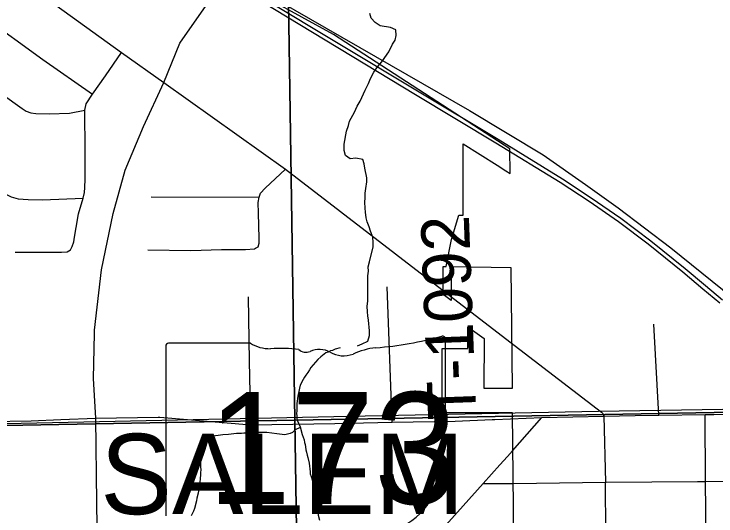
# Model space of a CAD drawing. Extents: x 0 to 34, y 0 to 22.
# Drawn here: x 4.199 to 5.027, y 17.129 to 17.721 of the extents above; entities that cross this region are included whole.
import ezdxf

# ---------------------------------------------------------------- set-up
doc = ezdxf.new("R2010")
doc.units = 0
for name, color, linetype in [('GM_X_City_Street', 7, 'Continuous'), ('GM_X_Corporation', 7, 'Continuous'), ('GM_X_Corporation_Text', 7, 'Continuous'), ('GM_X_County_Road', 7, 'Continuous'), ('GM_X_Minor_River', 7, 'Continuous'), ('GM_X_Rail_Line', 7, 'Continuous'), ('GM_X_Section', 7, 'Continuous'), ('GM_X_State_Location', 7, 'Continuous'), ('GM_X_State_Route', 7, 'Continuous'), ('GM_X_State_Shield', 7, 'Continuous'), ('GM_X_Township_Road', 7, 'Continuous'), ('GM_X_Township_Road_Text', 7, 'Continuous'), ('GM_X_US_Route', 7, 'Continuous')]:
    doc.layers.add(name, color=color, linetype=linetype)

msp = doc.modelspace()

# ---------------------------------------------------------------- linework, layer by layer
at = {"layer": 'GM_X_City_Street'}
for p, q in [((4.95935, 17.24777), (4.95332, 17.3552)), ((4.78787, 17.16729), (4.89625, 17.16873)), ((4.89686, 17.10104), (4.89625, 17.16873))]:
    msp.add_line(p, q, dxfattribs=at)
for points in [[(4.1481, 17.94458), (4.22468, 17.90127), (4.45612, 17.76798), (4.73588, 17.60688), (4.82274, 17.55459), (4.87294, 17.51962), (4.91128, 17.49207), (4.9734, 17.44512), (5.03441, 17.39587), (5.09354, 17.34622), (5.10314, 17.338), (5.1112, 17.33166), (5.11389, 17.32904), (5.1162, 17.32679)], [(5.01789, 16.75647), (5.01713, 16.84532), (5.01705, 16.85489), (5.01646, 16.92439), (5.01497, 17.10166), (5.01439, 17.16951), (5.01372, 17.24856)]]:
    msp.add_lwpolyline(points, dxfattribs=at)
at = {"layer": 'GM_X_Corporation'}
msp.add_lwpolyline([(4.7933, 16.6174), (4.78685, 17.25042), (4.74798, 17.25045), (4.70383, 17.25048), (4.70388, 17.32626), (4.73419, 17.32624), (4.7342, 17.35191), (4.75314, 17.33805), (4.7531, 17.27963), (4.78655, 17.27961), (4.78511, 17.42147), (4.71434, 17.42275), (4.71431, 17.38297), (4.70506, 17.39021), (4.70508, 17.42298), (4.70849, 17.42292), (4.7147, 17.45471), (4.72358, 17.48369), (4.72851, 17.4836), (4.72856, 17.56772), (4.76855, 17.54269), (4.77899, 17.53591), (4.78398, 17.53266), (4.78368, 17.56184), (4.57553, 17.69648), (4.50108, 17.73775)], dxfattribs=at)
at = {"layer": 'GM_X_County_Road'}
for p, q in [((4.8943, 17.24683), (4.89625, 17.16873)), ((4.78655, 17.2058), (4.82128, 17.24488))]:
    msp.add_line(p, q, dxfattribs=at)
for points in [[(4.30411, 16.68523), (4.39551, 16.6873), (4.41229, 16.68968), (4.4267, 16.69428), (4.44068, 16.6996), (4.45473, 16.71024), (4.46516, 16.71819), (4.47258, 16.72621), (4.47852, 16.73334), (4.58068, 16.92928), (4.59524, 16.96194), (4.60504, 16.97976), (4.61588, 17.00129), (4.62182, 17.01229), (4.63013, 17.02431), (4.65416, 17.05807), (4.75214, 17.16729), (4.77199, 17.18941), (4.78076, 17.19929), (4.78655, 17.2058)], [(5.00672, 17.16946), (5.01439, 17.16951), (5.16951, 17.17054), (5.1907, 17.17089), (5.22212, 17.17103), (5.46565, 17.18259), (5.54242, 17.1836)], [(4.89625, 17.16873), (4.89724, 17.16873), (5.00477, 17.16945)], [(5.00477, 17.16945), (5.00576, 17.16946), (5.00672, 17.16946)]]:
    msp.add_lwpolyline(points, dxfattribs=at)
at = {"layer": 'GM_X_Minor_River'}
for points in [[(4.60418, 17.32971), (4.60969, 17.33192), (4.61606, 17.3351), (4.61819, 17.34161), (4.61806, 17.34731), (4.61702, 17.35982), (4.61616, 17.36475), (4.61566, 17.36967), (4.61552, 17.37613), (4.61614, 17.38223), (4.616, 17.3883), (4.61623, 17.39515), (4.616, 17.4054), (4.61623, 17.41187), (4.61686, 17.41758), (4.61675, 17.42252), (4.61813, 17.42863), (4.61916, 17.4336), (4.6223, 17.44583), (4.62255, 17.45153), (4.62203, 17.4576), (4.61921, 17.46476), (4.61759, 17.46966), (4.61555, 17.4757), (4.61431, 17.48061), (4.6134, 17.48705), (4.61291, 17.49198), (4.61276, 17.49882), (4.61302, 17.50414), (4.6129, 17.50946), (4.61391, 17.51518), (4.61487, 17.52281), (4.61514, 17.52775), (4.61261, 17.5391), (4.61174, 17.54402), (4.61011, 17.5493), (4.60211, 17.55064), (4.5953, 17.55011), (4.58991, 17.55378), (4.58825, 17.55983), (4.58846, 17.56743), (4.59115, 17.5827), (4.59328, 17.5892), (4.59469, 17.59418), (4.60051, 17.60495), (4.60376, 17.61224), (4.60705, 17.61802), (4.6132, 17.63107), (4.61682, 17.63876), (4.61934, 17.64451), (4.62334, 17.65221), (4.62776, 17.65839), (4.63255, 17.66419), (4.63623, 17.6696), (4.64101, 17.67617), (4.64536, 17.685), (4.64828, 17.69001), (4.64968, 17.69536), (4.64915, 17.70219), (4.64302, 17.70471), (4.63084, 17.70672), (4.62468, 17.71076), (4.62001, 17.71597), (4.61838, 17.72126)], [(4.58337, 17.32733), (4.57774, 17.32557), (4.57472, 17.32402), (4.57207, 17.32361), (4.56943, 17.32206), (4.56679, 17.32126), (4.56077, 17.31663), (4.55739, 17.31355), (4.54916, 17.30395), (4.54729, 17.30127), (4.54543, 17.29821), (4.54319, 17.29514), (4.54171, 17.29247), (4.53984, 17.28978), (4.5365, 17.28328), (4.53578, 17.27947), (4.53362, 17.27033), (4.53258, 17.26158), (4.53265, 17.2555), (4.5323, 17.25283), (4.53195, 17.24979), (4.53236, 17.24713), (4.53239, 17.24447), (4.5328, 17.24182), (4.53631, 17.23388), (4.53868, 17.22517), (4.54103, 17.21873), (4.54145, 17.2157), (4.54223, 17.21305), (4.54264, 17.21039), (4.54306, 17.20698), (4.54385, 17.20432), (4.54465, 17.20053), (4.54544, 17.19788), (4.54704, 17.19106), (4.54829, 17.1812), (4.54832, 17.17854), (4.54949, 17.17551), (4.55303, 17.16415), (4.55382, 17.1615), (4.55503, 17.15506), (4.55629, 17.14443), (4.55633, 17.14101), (4.55759, 17.13), (4.55918, 17.12394)], [(4.5365, 17.23317), (4.53066, 17.23039), (4.52728, 17.22731), (4.52464, 17.22614), (4.51821, 17.22454), (4.51213, 17.22523), (4.50909, 17.22596), (4.49694, 17.22733), (4.49049, 17.22725), (4.48784, 17.22722), (4.48443, 17.2268), (4.48177, 17.22715), (4.47874, 17.22673), (4.47002, 17.22663), (4.46737, 17.22622), (4.4613, 17.22615), (4.45183, 17.22489), (4.44538, 17.22482), (4.44235, 17.2244), (4.43402, 17.22316), (4.431, 17.22237), (4.42836, 17.22082), (4.42574, 17.21813), (4.42312, 17.21468), (4.42202, 17.21162), (4.41984, 17.20361), (4.41914, 17.19791), (4.41917, 17.19525), (4.41882, 17.19258), (4.41889, 17.1865), (4.4193, 17.18385), (4.41897, 17.18004), (4.419, 17.17738), (4.41763, 17.16407), (4.41691, 17.1614), (4.41621, 17.15607), (4.41476, 17.14997), (4.41403, 17.14692), (4.41187, 17.13778), (4.41076, 17.13472), (4.40779, 17.12899)]]:
    msp.add_lwpolyline(points, dxfattribs=at)
at = {"layer": 'GM_X_Rail_Line'}
for points in [[(4.13393, 17.95003), (4.30457, 17.84736), (4.36362, 17.81219), (4.4911, 17.73532), (4.67239, 17.62597), (4.76723, 17.569), (4.84307, 17.52257), (4.87701, 17.50021), (4.91159, 17.4761), (4.9468, 17.44962), (4.98744, 17.41691), (5.01129, 17.39688), (5.03127, 17.38023)], [(4.13637, 17.95404), (4.307, 17.85138), (4.36604, 17.8162), (4.49353, 17.73933), (4.67482, 17.62998), (4.76968, 17.573), (4.8456, 17.52653), (4.87966, 17.50408), (4.91436, 17.47989), (4.94969, 17.45331), (4.99044, 17.42052), (5.01431, 17.40047), (5.03437, 17.38376)], [(5.15686, 17.25629), (4.88823, 17.25215), (4.61306, 17.24676), (3.47005, 17.2222), (2.51051, 17.21409), (2.1, 17.21062)]]:
    msp.add_lwpolyline(points, dxfattribs=at)
at = {"layer": 'GM_X_Section'}
for points in [[(4.51471, 18.25447), (5.53316, 18.2617), (5.54015, 17.2602), (4.52994, 17.24175)], [(4.51471, 18.25447), (4.52994, 17.24175), (3.52446, 17.2236), (3.47292, 17.22309), (3.45985, 18.23812)], [(5.54015, 17.2602), (5.54684, 16.2132), (4.54619, 16.19229), (4.52994, 17.24175)], [(4.52994, 17.24175), (4.54619, 16.19229), (3.5333, 16.18652), (3.52446, 17.2236)]]:
    msp.add_lwpolyline(points, close=True, dxfattribs=at)
at = {"layer": 'GM_X_State_Route'}
for p, q in [((4.29545, 17.24411), (4.36914, 17.24528)), ((4.8943, 17.24683), (4.93147, 17.24737)), ((4.93147, 17.24737), (4.95935, 17.24777)), ((4.95935, 17.24777), (5.01372, 17.24856)), ((4.25419, 17.2426), (4.29545, 17.24411)), ((4.29678, 17.14431), (4.29545, 17.24411))]:
    msp.add_line(p, q, dxfattribs=at)
for points in [[(4.1591, 17.79596), (4.1978, 17.76788), (4.32597, 17.67542), (4.37577, 17.64009), (4.51919, 17.5376), (4.77837, 17.33838)], [(4.37577, 17.64009), (4.39436, 17.68635), (4.42839, 17.73473), (4.44645, 17.75638), (4.45548, 17.7672)], [(4.29377, 17.34401), (4.29385, 17.34802), (4.30223, 17.41908), (4.31613, 17.48548), (4.33003, 17.53644), (4.35165, 17.58817), (4.37577, 17.64009)], [(4.29545, 17.24411), (4.29265, 17.29087), (4.29377, 17.34401)], [(4.77837, 17.33838), (4.89146, 17.25145), (4.89299, 17.25017), (4.89366, 17.24942), (4.8943, 17.24683)], [(4.36914, 17.24528), (4.37098, 17.24531), (4.47824, 17.2363), (4.57738, 17.23819), (4.64475, 17.23948), (4.71928, 17.24091), (4.76285, 17.2426)], [(4.76285, 17.2426), (4.76582, 17.24272), (4.82128, 17.24488), (4.8943, 17.24683)], [(5.01372, 17.24856), (5.02115, 17.24867), (5.02419, 17.24872)], [(5.02419, 17.24872), (5.29436, 17.25264), (5.30867, 17.25285)], [(4.11923, 17.2396), (4.21912, 17.24131), (4.25419, 17.2426)], [(4.30246, 16.77504), (4.29973, 16.92274), (4.29678, 17.14431)]]:
    msp.add_lwpolyline(points, dxfattribs=at)
at = {"layer": 'GM_X_State_Shield'}
for p, q in [((4.70758, 17.23285), (4.70758, 17.33754)), ((4.37799, 17.32914), (4.37799, 17.12902)), ((4.47776, 17.33258), (4.38124, 17.33258)), ((4.70754, 17.23288), (4.70758, 17.23285))]:
    msp.add_line(p, q, dxfattribs=at)
for centre, major_axis, start_param, end_param in [((4.59017, 17.60541), (0.34952, 0), 4.814394, 5.042369), ((4.70392, 17.33797), (0.00367, 0), 6.141152, 7.989035), ((4.38177, 17.32956), (0.00382, 0), 1.712693, 3.28349), ((4.50074, 17.35581), (0.03703, 0), 4.042523, 4.731795), ((4.51302, 17.22023), (0.13295, 0), 1.404758, 1.657858), ((4.54321, 17.3306), (0.01068, 0), 3.836095, 5.185415), ((4.55889, 17.30747), (0.02221, 0), 0.950623, 2.079405), ((4.58756, 17.33919), (0.02672, 0), 4.081561, 5.145723), ((4.63476, 17.27146), (0.07032, 0), 1.699011, 2.107814), ((4.70673, 17.22517), (0.00568, 0), 1.883978, 3.671073), ((4.70366, 17.23245), (0.00393, 0), 5.05454, 6.418171), ((4.6706, 17.21194), (0.03409, 0), 5.934695, 6.695948), ((4.72072, 17.18904), (0.0248, 0), 2.387724, 3.262537), ((4.60975, 17.17573), (0.08742, 0), 5.101752, 6.440018)]:
    msp.add_ellipse(centre, major_axis=major_axis, ratio=0.8, start_param=start_param, end_param=end_param, dxfattribs=at)
at = {"layer": 'GM_X_Township_Road'}
for p, q in [((4.36072, 17.50536), (4.48792, 17.50459)), ((4.64475, 17.23948), (4.63908, 17.39896)), ((4.75214, 17.16729), (4.78787, 17.16729))]:
    msp.add_line(p, q, dxfattribs=at)
for points in [[(4.10724, 17.75359), (4.11943, 17.74842), (4.16213, 17.718), (4.23313, 17.66692), (4.29162, 17.62639)], [(3.97718, 17.70937), (4.04337, 17.70884), (4.05529, 17.70884), (4.06792, 17.70777), (4.07522, 17.70617), (4.12789, 17.66934), (4.18509, 17.62628), (4.20866, 17.60911), (4.21329, 17.60626), (4.21872, 17.6043), (4.22468, 17.60333), (4.24042, 17.60297), (4.26462, 17.60395), (4.2825, 17.60742)], [(4.28308, 17.56594), (4.28313, 17.57619), (4.28268, 17.58981), (4.2825, 17.60742), (4.28402, 17.61462), (4.29162, 17.62639), (4.30706, 17.64782), (4.32597, 17.67542)], [(4.02142, 17.62869), (4.05078, 17.60676), (4.07158, 17.59139), (4.08953, 17.5799), (4.14779, 17.53752), (4.17672, 17.51578), (4.18295, 17.51223), (4.18847, 17.50867), (4.19576, 17.50529), (4.20395, 17.5028), (4.21587, 17.50191), (4.23277, 17.50173), (4.28046, 17.50351)], [(4.2616, 17.44025), (4.26551, 17.44283), (4.26764, 17.44675), (4.26943, 17.45227), (4.27032, 17.45778), (4.27227, 17.46899), (4.27512, 17.48518), (4.28046, 17.50351), (4.28206, 17.51027), (4.28259, 17.51632), (4.28295, 17.5261), (4.28313, 17.53482), (4.28303, 17.55466), (4.28308, 17.56594)], [(4.48792, 17.50459), (4.48947, 17.50961), (4.49506, 17.5154), (4.51919, 17.5376)], [(4.48263, 17.44393), (4.4837, 17.44458), (4.48676, 17.44629), (4.48811, 17.45074), (4.48811, 17.45653), (4.48715, 17.48606), (4.48676, 17.49861), (4.48792, 17.50459)], [(4.35686, 17.44282), (4.40743, 17.44205), (4.44372, 17.44301), (4.46051, 17.44321), (4.47209, 17.44321), (4.48263, 17.44393)], [(4.20039, 17.43999), (4.22494, 17.43999), (4.24007, 17.43999), (4.25519, 17.43981), (4.2616, 17.44025)], [(4.47824, 17.2363), (4.47662, 17.31128), (4.47537, 17.38715)]]:
    msp.add_lwpolyline(points, dxfattribs=at)
at = {"layer": 'GM_X_US_Route'}
msp.add_line((4.25419, 17.2426), (4.29545, 17.24411), dxfattribs=at)
for points in [[(4.37577, 17.64009), (4.39436, 17.68635), (4.42839, 17.73473), (4.44645, 17.75638), (4.45548, 17.7672)], [(4.29377, 17.34401), (4.29385, 17.34802), (4.30223, 17.41908), (4.31613, 17.48548), (4.33003, 17.53644), (4.35165, 17.58817), (4.37577, 17.64009)], [(4.29545, 17.24411), (4.29265, 17.29087), (4.29377, 17.34401)], [(4.11923, 17.2396), (4.21912, 17.24131), (4.25419, 17.2426)]]:
    msp.add_lwpolyline(points, dxfattribs=at)

# ---------------------------------------------------------------- texts
at = {"layer": 'GM_X_Corporation_Text'}
msp.add_text('SALEM', height=0.094697, rotation=0.00001, dxfattribs=at).set_placement((4.3008, 17.13113))
at = {"layer": 'GM_X_State_Location'}
for s, p in [('s', (4.53908, 17.21577)), ('r', (4.53907, 17.21577))]:
    msp.add_text(s, height=0.000189, dxfattribs=at).set_placement(p)
msp.add_text('173', height=0.000189, rotation=0.00001, dxfattribs=at).set_placement((4.47222, 17.20199))
at = {"layer": 'GM_X_State_Shield'}
msp.add_text('173', height=0.131836, dxfattribs=at).set_placement((4.42746, 17.14313))
at = {"layer": 'GM_X_Township_Road_Text'}
msp.add_text('T-1092', height=0.056818, rotation=92.10352, dxfattribs=at).set_placement((4.7441, 17.24366))

doc.saveas('drawing.dxf')
